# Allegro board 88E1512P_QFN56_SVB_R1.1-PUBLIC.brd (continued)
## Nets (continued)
N171469831: D2.2 R29.1
N192245170: D10.2 Q2.3(COLLECTOR)
N192245172: Q2.1(BASE) R127.2
N192284111: D8.2 Q1.3(COLLECTOR)
N192284251: Q1.1(BASE) R112.2

Pads without a net: SKT1 1 2 3 4; SKT2 1 2 3 4; U4 8 11; U6 13 14 15 16; U7 7; U8 7; U9 2 10; U10 2 10; U11 2 10; U12 2 10

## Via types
v1: diameter 0.559, hole 0.305, TOP to BOTTOM, 643 vias

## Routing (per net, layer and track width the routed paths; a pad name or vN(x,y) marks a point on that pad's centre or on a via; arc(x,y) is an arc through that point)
GND: length 1569
  TOP w0.254: v1(20.33,20.46) 19.81,20.98 U9.16 ; U10.16 156.6,175.69 v1(156.08,176.21) ; v1(176.4,178.75) 176.92,178.23 U12.16 ; U11.16 114.38,178.32 v1(113.86,177.8)
  TOP w0.508: C104.2 v1(146.43,40.13) ; v1(47.37,183.01) SW1.2 46.67,184.98 v1(46.1,184.4) ; J16.2 11.18,157.99 v1(11.18,157.1) ; v1(20.29,155.32) 20.29,154.41 J15.4 ; v1(87.38,155.32) 87.38,154.43 J12.5 ; J12.3 83.79,158.01 v1(83.79,157.1) ; J15.3 23.9,154.41 v1(23.9,155.32) ; v1(61.98,162.94) 61.98,162.05 J13.5 ; J11.5 100.08,154.43 v1(100.08,155.32) ; C128.2 57.44,20.84 v1(56.55,20.84) ; U7.10 v1(84.97,174.09) ; C115.2 v1(133.6,40.1) ; v1(71.09,164.72) 71.09,165.63 J14.3 ; J14.2 71.12,162.05 v1(71.12,162.94) ; J13.4 62,165.63 v1(62,164.72) ; J13.3 58.39,165.63 v1(58.39,164.72) ; U8.3 v1(32.15,174.09) ; C106.2 143.51,40.01 v1(143.38,40.13) ; J12.4 87.4,158.01 v1(87.4,157.1) ; v1(7.59,155.32) 7.59,154.41 J16.4 ; J14.4 74.7,165.63 v1(74.7,164.72) ; U7.9 v1(85.77,174.09) ; J18.2 20.19,119.25 v1(20.19,120.14) ; C135.2 v1(43.69,26.51) ; U7.1 v1(92.17,174.09) ; Q2.2 v1(119.57,168.97) ; J15.2 23.88,157.99 v1(23.88,157.1) ; U8.20 v1(34.15,168.81) ; v1(7.47,121.92) 7.47,122.83 J17.3 ; v1(23.77,121.92) 23.77,122.83 J18.4 ; J17.4 11.07,122.83 v1(11.07,121.92) ; C112.2 138.68,40.01 v1(138.81,40.13) ; v1(148.24,180.59) 148.85,180.59 C51.2 ; C125.2 v1(61.94,25.56) ; v1(96.49,157.1) 96.49,158.01 J11.3 ; J13.2 58.42,162.05 v1(58.42,162.94) ; J14.5 74.68,162.05 v1(74.68,162.94) ; C133.2 v1(43.69,24.29) ; v1(23.75,120.14) 23.75,119.25 J18.5 ; J16.3 11.2,154.41 v1(11.2,155.32) ; J11.4 100.1,158.01 v1(100.1,157.1) ; D9.2 164.77,163.83 v1(164.79,163.81) ; v1(59.56,20.84) 59.55,20.82 C129.2 ; C131.2 v1(46.23,20.82) ; J16.5 7.62,157.99 v1(7.62,157.1) ; v1(47.37,176.4) SW1.3 v1(47.37,180.09) ; C124.2 v1(61.94,26.67) ; v1(11.05,120.14) 11.05,119.25 J17.5 ; C130.2 v1(44.8,23.02) ; C134.2 v1(43.69,25.4) ; Y1.2 v1(167.51,100.33) ; v1(20.17,121.92) 20.17,122.83 J18.3 ; v1(59.63,182.02) 59.63,182.63 60.23,183.23 U3.1 ; v1(7.49,120.14) 7.49,119.25 J17.2 ; C132.2 v1(49.24,20.82) ; D11.2 v1(167.7,182.88) ; U7.17 v1(90.17,168.81) ; U8.11 v1(26.95,168.81) ; D7.2 v1(149.91,198.88) ; J15.5 20.32,157.99 v1(20.32,157.1) ; v1(96.52,155.32) 96.52,154.43 J11.2 ; C7.2 v1(168.56,89.54) C6.2 ; C107.2 141.48,40.01 v1(141.61,40.13) ; U8.14 v1(29.35,168.81) ; Y3.2 v1(74.68,99.89) ; v1(137.8,40.13) 137.67,40.01 C111.2 ; U8.9 v1(27.35,174.09) ; C108.2 v1(142.49,40.13) ; C102.2 145.42,40.01 v1(145.54,40.13) ; U8.17 v1(31.75,168.81) ; U8.10 v1(26.55,174.09) ; U8.1 v1(33.75,174.09) ; U7.11 v1(85.37,168.81) ; v1(83.82,155.32) 83.82,154.43 J12.2 ; U7.3 v1(90.57,174.09) ; C126.2 v1(61.94,24.45) ; C103.2 v1(147.57,40.13) ; Q1.2 v1(26.61,35.75) ; C116.2 v1(134.75,40.1) ; U7.20 v1(92.57,168.81) ; C114.2 v1(135.89,40.1) ; C127.2 v1(60.67,23.02) ; U7.14 v1(87.77,168.81) ; C110.2 v1(139.83,40.1)
  TOP w0.762: C123.1 v1(9.78,21.11) ; C122.1 v1(175.13,30.61)
  TOP w2.54: J21.1 J21.2
  L2_GND w1.27: TP11.1 23.41,107.53 ; TP11.1 21.8,109.14 ; TP11.1 21.8,107.53 ; TP11.1 23.41,109.14 ; TP4.1 24.55,77.77 ; TP4.1 22.94,76.16 ; TP4.1 22.94,77.77 ; TP4.1 24.55,76.16 ; J27.4 115.97,142.09 ; J27.4 115.97,144.42 ; J27.4 113.64,142.09 ; J27.4 113.64,144.42 ; J30.2 112.04,42.65 ; J30.2 112.04,44.98 ; J30.2 109.71,42.65 ; J30.2 109.71,44.98 ; 10.77,65.51 J29.5 ; J29.5 13.1,67.84 ; J29.5 10.77,67.84 ; J29.5 13.1,65.51 ; 7.49,98.68 8.66,97.51 ; 7.49,98.68 6.33,99.84 ; 7.49,98.68 8.66,99.84 ; 7.49,98.68 6.33,97.51 ; 188.45,125.75 189.61,124.59 ; 189.61,124.59 190.78,123.42 ; 189.61,124.59 188.45,123.42 ; 189.61,124.59 190.78,125.75 ; 94.09,76.98 J23.3 ; J23.3 96.41,76.98 ; J23.3 96.41,74.65 ; J23.3 94.09,74.65 ; J26.3 61.49,136.29 ; J26.3 59.16,133.96 ; J26.3 59.16,136.29 ; J26.3 61.49,133.96 ; 34.52,53.45 J31.4 ; J31.4 36.85,53.45 ; J31.4 34.52,55.77 ; J31.4 36.85,55.77 ; 5.69,60.43 J29.3 ; J29.3 5.69,62.76 ; J29.3 8.02,60.43 ; J29.3 8.02,62.76 ; 105.49,170.52 TP12.1 ; TP12.1 105.49,172.13 ; TP12.1 107.1,172.13 ; TP12.1 107.1,170.52 ; J9.4 139.06,192.28 ; J9.4 137.54,192.28 ; J9.4 139.06,193.8 ; J9.4 137.54,193.8 ; 7.2,81.96 TP13.1 ; TP13.1 8.81,81.96 ; TP13.1 7.2,80.35 ; TP13.1 8.81,80.35 ; 99.17,69.57 J23.5 ; J23.5 101.49,71.9 ; J23.5 101.49,69.57 ; J23.5 99.17,71.9 ; 84.18,82.4 J8.3 ; J8.3 86.51,82.4 ; J8.3 84.18,84.73 ; J8.3 86.51,84.73 ; JP1.2 182.67,98.64 ; JP1.2 181.06,100.25 ; JP1.2 181.06,98.64 ; JP1.2 182.67,100.25 ; J27.5 115.97,147.17 ; J27.5 113.64,149.5 ; J27.5 113.64,147.17 ; J27.5 115.97,149.5 ; 189.84,86.47 J6.5 ; J6.5 192.17,86.47 ; J6.5 192.17,88.79 ; J6.5 189.84,88.79 ; J3.2 163.6,141.75 ; J3.2 161.27,141.75 ; J3.2 161.27,139.42 ; J3.2 163.6,139.42 ; J31.5 36.85,60.85 ; J31.5 36.85,58.53 ; J31.5 34.52,58.53 ; J31.5 34.52,60.85 ; J22.2 176.81,151.62 ; J22.2 174.48,151.62 ; J22.2 174.48,153.95 ; J22.2 176.81,153.95 ; 94.47,105.56 J2.2 ; J2.2 94.47,103.23 ; J2.2 96.8,103.23 ; J2.2 96.8,105.56 ; 189.84,48.15 J19.5 ; J19.5 192.17,48.15 ; J19.5 192.17,45.83 ; J19.5 189.84,45.83 ; 15.58,170.01 TP3.1 ; TP3.1 15.58,171.62 ; TP3.1 17.19,171.62 ; TP3.1 17.19,170.01 ; J6.4 192.17,83.71 ; J6.4 189.84,81.39 ; J6.4 189.84,83.71 ; J6.4 192.17,81.39 ; J27.3 110.89,142.09 ; J27.3 108.56,144.42 ; J27.3 108.56,142.09 ; J27.3 110.89,144.42 ; J6.2 187.09,88.79 ; J6.2 184.76,86.47 ; J6.2 187.09,86.47 ; J6.2 184.76,88.79 ; 65.41,135.13 66.57,133.96 ; 65.41,135.13 64.24,136.29 ; 65.41,135.13 66.57,136.29 ; 65.41,135.13 64.24,133.96 ; 84.18,87.48 J8.2 ; J8.2 86.51,87.48 ; J8.2 86.51,89.81 ; J8.2 84.18,89.81 ; 145.52,145.44 J24.3 ; J24.3 145.52,143.11 ; J24.3 147.85,143.11 ; J24.3 147.85,145.44 ; 92.18,50.69 J28.3 ; J28.3 94.51,50.69 ; J28.3 94.51,48.37 ; J28.3 92.18,48.37 ; J19.3 187.09,40.75 ; J19.3 184.76,43.07 ; J19.3 187.09,43.07 ; J19.3 184.76,40.75 ; J30.3 112.04,39.9 ; J30.3 109.71,39.9 ; J30.3 109.71,37.57 ; J30.3 112.04,37.57 ; 10.77,60.43 J29.4 ; J29.4 13.1,62.76 ; J29.4 13.1,60.43 ; J29.4 10.77,62.76 ; 5.69,67.84 J29.2 ; J29.2 8.02,65.51 ; J29.2 8.02,67.84 ; J29.2 5.69,65.51 ; 193.02,99.59 194.18,98.43 ; 194.18,98.43 195.35,99.59 ; 194.18,98.43 195.35,97.26 ; 194.18,98.43 193.02,97.26 ; 87.1,50.69 88.27,49.53 ; 88.27,49.53 89.43,50.69 ; 88.27,49.53 87.1,48.37 ; 88.27,49.53 89.43,48.37 ; 82.76,104.44 JP7.2 ; JP7.2 84.37,104.44 ; JP7.2 84.37,102.83 ; JP7.2 82.76,102.83 ; J22.3 176.81,148.87 ; J22.3 174.48,148.87 ; J22.3 176.81,146.54 ; J22.3 174.48,146.54 ; 99.55,105.56 J2.5 ; J2.5 101.88,103.23 ; J2.5 99.55,103.23 ; J2.5 101.88,105.56 ; 175.6,50.63 JP6.2 ; JP6.2 177.21,52.24 ; JP6.2 175.6,52.24 ; JP6.2 177.21,50.63 ; 184.49,187.5 TP9.1 ; TP9.1 186.1,185.88 ; TP9.1 184.49,185.88 ; TP9.1 186.1,187.5 ; J31.3 31.77,55.77 ; J31.3 31.77,53.45 ; J31.3 29.44,53.45 ; J31.3 29.44,55.77 ; 33.1,20.53 TP10.1 ; TP10.1 34.71,22.14 ; TP10.1 34.71,20.53 ; TP10.1 33.1,22.14 ; 114.79,39.9 115.95,38.73 ; 115.95,38.73 114.79,37.57 ; 115.95,38.73 117.12,37.57 ; 115.95,38.73 117.12,39.9 ; J4.3 190.78,120.67 ; J4.3 190.78,118.34 ; J4.3 188.45,120.67 ; J4.3 188.45,118.34 ; 173.06,45.26 TP5.1 ; TP5.1 173.06,43.64 ; TP5.1 174.67,43.64 ; TP5.1 174.67,45.26 ; 11.41,97.51 12.57,98.68 ; 12.57,98.68 13.74,99.84 ; 12.57,98.68 11.41,99.84 ; 12.57,98.68 13.74,97.51 ; 6.33,94.76 J10.3 ; J10.3 8.66,92.43 ; J10.3 6.33,92.43 ; J10.3 8.66,94.76 ; 89.26,89.81 J8.5 ; J8.5 91.59,87.48 ; J8.5 89.26,87.48 ; J8.5 91.59,89.81 ; 193.53,125.75 194.69,124.59 ; 194.69,124.59 193.53,123.42 ; 194.69,124.59 195.86,123.42 ; 194.69,124.59 195.86,125.75 ; J31.2 31.77,60.85 ; J31.2 29.44,58.53 ; J31.2 31.77,58.53 ; J31.2 29.44,60.85 ; 64.24,139.04 65.41,140.21 ; 65.41,140.21 64.24,141.37 ; 65.41,140.21 66.57,139.04 ; 65.41,140.21 66.57,141.37 ; 179.56,148.87 J22.4 ; J22.4 179.56,146.54 ; J22.4 181.89,148.87 ; J22.4 181.89,146.54 ; 173.08,192.93 J21.1 ; J21.1 175.41,192.93 ; J21.1 173.08,190.61 ; J21.1 175.41,190.61 ; 193.02,102.34 J1.5 ; J1.5 195.35,102.34 ; J1.5 193.02,104.67 ; J1.5 195.35,104.67 ; 22.69,88.09 JP8.2 ; JP8.2 22.69,89.71 ; JP8.2 24.3,89.71 ; JP8.2 24.3,88.09 ; 184.76,62.97 J7.2 ; J7.2 187.09,62.97 ; J7.2 184.76,65.3 ; J7.2 187.09,65.3 ; 145.52,148.19 J24.2 ; J24.2 145.52,150.52 ; J24.2 147.85,150.52 ; J24.2 147.85,148.19 ; J28.4 94.51,53.45 ; J28.4 94.51,55.77 ; J28.4 92.18,53.45 ; J28.4 92.18,55.77 ; 88.27,54.61 89.43,53.45 ; 88.27,54.61 87.1,53.45 ; 88.27,54.61 87.1,55.77 ; 88.27,54.61 89.43,55.77 ; J2.4 101.88,98.15 ; J2.4 99.55,100.48 ; J2.4 101.88,100.48 ; J2.4 99.55,98.15 ; 63.84,179.88 JP2.1 ; JP2.1 63.84,178.26 ; JP2.1 65.45,179.88 ; JP2.1 65.45,178.26 ; J5.2 190.78,140.44 ; J5.2 190.78,142.77 ; J5.2 188.45,140.44 ; J5.2 188.45,142.77 ; 187.94,104.67 J1.2 ; J1.2 190.27,104.67 ; J1.2 190.27,102.34 ; J1.2 187.94,102.34 ; 189.84,60.22 J7.4 ; J7.4 189.84,57.89 ; J7.4 192.17,60.22 ; J7.4 192.17,57.89 ; J27.2 110.89,149.5 ; J27.2 108.56,147.17 ; J27.2 108.56,149.5 ; J27.2 110.89,147.17 ; 114.79,44.98 115.95,43.81 ; 115.95,43.81 114.79,42.65 ; 115.95,43.81 117.12,44.98 ; 115.95,43.81 117.12,42.65 ; J19.2 187.09,48.15 ; J19.2 184.76,45.83 ; J19.2 184.76,48.15 ; J19.2 187.09,45.83 ; 39.09,133.96 J25.3 ; J25.3 39.09,136.29 ; J25.3 41.42,133.96 ; J25.3 41.42,136.29 ; 166.35,139.42 J3.5 ; J3.5 168.68,139.42 ; J3.5 166.35,141.75 ; J3.5 168.68,141.75 ; J7.3 187.09,60.22 ; J7.3 187.09,57.89 ; J7.3 184.76,57.89 ; J7.3 184.76,60.22 ; J25.2 41.42,139.04 ; J25.2 41.42,141.37 ; J25.2 39.09,141.37 ; J25.2 39.09,139.04 ; J4.4 195.86,120.67 ; J4.4 195.86,118.34 ; J4.4 193.53,120.67 ; J4.4 193.53,118.34 ; 99.17,76.98 J23.2 ; J23.2 101.49,76.98 ; J23.2 99.17,74.65 ; J23.2 101.49,74.65 ; 89.26,82.4 J8.4 ; J8.4 91.59,82.4 ; J8.4 89.26,84.73 ; J8.4 91.59,84.73 ; 44.17,133.96 J25.4 ; J25.4 46.5,133.96 ; J25.4 44.17,136.29 ; J25.4 46.5,136.29 ; 173.08,200.77 J21.2 ; J21.2 175.41,203.09 ; J21.2 175.41,200.77 ; J21.2 173.08,203.09 ; 12.57,93.6 13.74,94.76 ; 12.57,93.6 11.41,92.43 ; 12.57,93.6 13.74,92.43 ; 12.57,93.6 11.41,94.76 ; 150.6,143.11 J24.4 ; J24.4 152.93,145.44 ; J24.4 150.6,145.44 ; J24.4 152.93,143.11 ; JP4.2 99.36,87.29 ; JP4.2 97.75,85.68 ; JP4.2 99.36,85.68 ; JP4.2 97.75,87.29 ; J3.3 163.6,136.67 ; J3.3 161.27,134.34 ; J3.3 163.6,134.34 ; J3.3 161.27,136.67 ; 189.84,62.97 J7.5 ; J7.5 192.17,62.97 ; J7.5 189.84,65.3 ; J7.5 192.17,65.3 ; J2.3 96.8,100.48 ; J2.3 94.47,98.15 ; J2.3 96.8,98.15 ; J2.3 94.47,100.48 ; 136.23,179.53 TP2.1 ; TP2.1 137.84,179.53 ; TP2.1 137.84,181.15 ; TP2.1 136.23,181.15 ; TP8.1 106.22,24.47 ; TP8.1 106.22,26.08 ; TP8.1 104.6,24.47 ; TP8.1 104.6,26.08 ; J5.4 195.86,135.36 ; J5.4 195.86,137.69 ; J5.4 193.53,135.36 ; J5.4 193.53,137.69 ; 166.35,136.67 J3.4 ; J3.4 166.35,134.34 ; J3.4 168.68,134.34 ; J3.4 168.68,136.67 ; J5.3 190.78,135.36 ; J5.3 188.45,135.36 ; J5.3 190.78,137.69 ; J5.3 188.45,137.69 ; 138.81,189.74 J9.3 ; J9.3 138.81,191.26 ; J9.3 140.33,191.26 ; J9.3 140.33,189.74 ; J5.5 195.86,142.77 ; J5.5 193.53,142.77 ; J5.5 193.53,140.44 ; J5.5 195.86,140.44 ; J24.5 152.93,148.19 ; J24.5 150.6,148.19 ; J24.5 152.93,150.52 ; J24.5 150.6,150.52 ; 187.94,99.59 189.1,98.43 ; 189.1,98.43 190.27,97.26 ; 189.1,98.43 187.94,97.26 ; 189.1,98.43 190.27,99.59 ; 58.12,176.07 TP1.1 ; TP1.1 59.73,174.45 ; TP1.1 58.12,174.45 ; TP1.1 59.73,176.07 ; J6.3 187.09,83.71 ; J6.3 184.76,83.71 ; J6.3 187.09,81.39 ; J6.3 184.76,81.39 ; J26.2 61.49,139.04 ; J26.2 61.49,141.37 ; J26.2 59.16,139.04 ; J26.2 59.16,141.37 ; J19.4 192.17,40.75 ; J19.4 192.17,43.07 ; J19.4 189.84,40.75 ; J19.4 189.84,43.07 ; 94.09,69.57 J23.4 ; J23.4 94.09,71.9 ; J23.4 96.41,69.57 ; J23.4 96.41,71.9 ; J25.5 46.5,139.04 ; J25.5 44.17,139.04 ; J25.5 44.17,141.37 ; J25.5 46.5,141.37 ; 79.71,69.3 JP10.2 ; JP10.2 81.32,70.91 ; JP10.2 81.32,69.3 ; JP10.2 79.71,70.91 ; J22.5 181.89,151.62 ; J22.5 179.56,153.95 ; J22.5 181.89,153.95 ; J22.5 179.56,151.62
  L5_GND w1.27: 39.09,133.96 J25.3 ; J25.3 41.42,133.96 ; J25.3 39.09,136.29 ; J25.3 41.42,136.29 ; J8.4 91.59,84.73 ; J8.4 89.26,84.73 ; J8.4 91.59,82.4 ; J8.4 89.26,82.4 ; 44.17,133.96 J25.4 ; J25.4 46.5,136.29 ; J25.4 46.5,133.96 ; J25.4 44.17,136.29 ; J5.2 190.78,140.44 ; J5.2 190.78,142.77 ; J5.2 188.45,142.77 ; J5.2 188.45,140.44 ; 114.79,42.65 115.95,43.81 ; 115.95,43.81 117.12,44.98 ; 115.95,43.81 114.79,44.98 ; 115.95,43.81 117.12,42.65 ; 6.33,97.51 7.49,98.68 ; 7.49,98.68 8.66,99.84 ; 7.49,98.68 6.33,99.84 ; 7.49,98.68 8.66,97.51 ; 187.94,97.26 189.1,98.43 ; 189.1,98.43 187.94,99.59 ; 189.1,98.43 190.27,99.59 ; 189.1,98.43 190.27,97.26 ; 11.41,94.76 12.57,93.6 ; 12.57,93.6 13.74,92.43 ; 12.57,93.6 11.41,92.43 ; 12.57,93.6 13.74,94.76 ; 92.18,48.37 J28.3 ; J28.3 92.18,50.69 ; J28.3 94.51,48.37 ; J28.3 94.51,50.69 ; 184.76,65.3 J7.2 ; J7.2 184.76,62.97 ; J7.2 187.09,62.97 ; J7.2 187.09,65.3 ; J23.4 96.41,69.57 ; J23.4 96.41,71.9 ; J23.4 94.09,71.9 ; J23.4 94.09,69.57 ; J27.4 115.97,142.09 ; J27.4 113.64,142.09 ; J27.4 115.97,144.42 ; J27.4 113.64,144.42 ; 184.49,187.5 TP9.1 ; TP9.1 184.49,185.88 ; TP9.1 186.1,187.5 ; TP9.1 186.1,185.88 ; J29.3 8.02,62.76 ; J29.3 5.69,62.76 ; J29.3 8.02,60.43 ; J29.3 5.69,60.43 ; 34.52,53.45 J31.4 ; J31.4 36.85,55.77 ; J31.4 34.52,55.77 ; J31.4 36.85,53.45 ; JP8.2 24.3,88.09 ; JP8.2 24.3,89.71 ; JP8.2 22.69,89.71 ; JP8.2 22.69,88.09 ; 114.79,39.9 115.95,38.73 ; 115.95,38.73 114.79,37.57 ; 115.95,38.73 117.12,39.9 ; 115.95,38.73 117.12,37.57 ; 138.81,189.74 J9.3 ; J9.3 140.33,191.26 ; J9.3 140.33,189.74 ; J9.3 138.81,191.26 ; J19.3 187.09,40.75 ; J19.3 184.76,40.75 ; J19.3 184.76,43.07 ; J19.3 187.09,43.07 ; J2.5 101.88,105.56 ; J2.5 99.55,105.56 ; J2.5 99.55,103.23 ; J2.5 101.88,103.23 ; 193.02,104.67 J1.5 ; J1.5 193.02,102.34 ; J1.5 195.35,104.67 ; J1.5 195.35,102.34 ; J25.5 46.5,139.04 ; J25.5 44.17,141.37 ; J25.5 46.5,141.37 ; J25.5 44.17,139.04 ; J30.3 112.04,39.9 ; J30.3 112.04,37.57 ; J30.3 109.71,39.9 ; J30.3 109.71,37.57 ; J25.2 41.42,141.37 ; J25.2 39.09,139.04 ; J25.2 39.09,141.37 ; J25.2 41.42,139.04 ; 193.02,97.26 194.18,98.43 ; 194.18,98.43 195.35,97.26 ; 194.18,98.43 193.02,99.59 ; 194.18,98.43 195.35,99.59 ; J8.3 86.51,84.73 ; J8.3 86.51,82.4 ; J8.3 84.18,84.73 ; J8.3 84.18,82.4 ; 161.27,141.75 J3.2 ; J3.2 163.6,141.75 ; J3.2 163.6,139.42 ; J3.2 161.27,139.42 ; 82.76,104.44 JP7.2 ; JP7.2 82.76,102.83 ; JP7.2 84.37,104.44 ; JP7.2 84.37,102.83 ; J6.3 187.09,81.39 ; J6.3 187.09,83.71 ; J6.3 184.76,81.39 ; J6.3 184.76,83.71 ; 189.84,65.3 J7.5 ; J7.5 189.84,62.97 ; J7.5 192.17,65.3 ; J7.5 192.17,62.97 ; JP4.2 99.36,87.29 ; JP4.2 97.75,85.68 ; JP4.2 99.36,85.68 ; JP4.2 97.75,87.29 ; JP1.2 182.67,98.64 ; JP1.2 181.06,100.25 ; JP1.2 182.67,100.25 ; JP1.2 181.06,98.64 ; 59.16,133.96 J26.3 ; J26.3 61.49,133.96 ; J26.3 61.49,136.29 ; J26.3 59.16,136.29 ; J3.3 163.6,136.67 ; J3.3 161.27,134.34 ; J3.3 163.6,134.34 ; J3.3 161.27,136.67 ; J2.3 96.8,100.48 ; J2.3 96.8,98.15 ; J2.3 94.47,98.15 ; J2.3 94.47,100.48 ; 87.1,48.37 88.27,49.53 ; 88.27,49.53 89.43,50.69 ; 88.27,49.53 89.43,48.37 ; 88.27,49.53 87.1,50.69 ; 188.45,135.36 J5.3 ; J5.3 190.78,137.69 ; J5.3 190.78,135.36 ; J5.3 188.45,137.69 ; 15.58,171.62 TP3.1 ; TP3.1 17.19,171.62 ; TP3.1 17.19,170.01 ; TP3.1 15.58,170.01 ; J31.3 31.77,53.45 ; J31.3 29.44,55.77 ; J31.3 31.77,55.77 ; J31.3 29.44,53.45 ; 174.48,151.62 J22.2 ; J22.2 176.81,151.62 ; J22.2 174.48,153.95 ; J22.2 176.81,153.95 ; J27.5 115.97,147.17 ; J27.5 115.97,149.5 ; J27.5 113.64,149.5 ; J27.5 113.64,147.17 ; 193.53,137.69 J5.4 ; J5.4 195.86,137.69 ; J5.4 193.53,135.36 ; J5.4 195.86,135.36 ; 184.76,45.83 J19.2 ; J19.2 184.76,48.15 ; J19.2 187.09,45.83 ; J19.2 187.09,48.15 ; J27.3 110.89,144.42 ; J27.3 108.56,142.09 ; J27.3 110.89,142.09 ; J27.3 108.56,144.42 ; 7.2,81.96 TP13.1 ; TP13.1 7.2,80.35 ; TP13.1 8.81,81.96 ; TP13.1 8.81,80.35 ; J7.4 192.17,57.89 ; J7.4 192.17,60.22 ; J7.4 189.84,57.89 ; J7.4 189.84,60.22 ; J3.4 168.68,136.67 ; J3.4 166.35,136.67 ; J3.4 168.68,134.34 ; J3.4 166.35,134.34 ; J26.2 61.49,141.37 ; J26.2 59.16,139.04 ; J26.2 59.16,141.37 ; J26.2 61.49,139.04 ; 22.94,77.77 TP4.1 ; TP4.1 24.55,76.16 ; TP4.1 22.94,76.16 ; TP4.1 24.55,77.77 ; 193.53,118.34 J4.4 ; J4.4 195.86,118.34 ; J4.4 193.53,120.67 ; J4.4 195.86,120.67 ; 175.6,52.24 JP6.2 ; JP6.2 177.21,52.24 ; JP6.2 175.6,50.63 ; JP6.2 177.21,50.63 ; J21.2 175.41,203.09 ; J21.2 173.08,203.09 ; J21.2 173.08,200.77 ; J21.2 175.41,200.77 ; J22.3 176.81,148.87 ; J22.3 174.48,148.87 ; J22.3 176.81,146.54 ; J22.3 174.48,146.54 ; J6.5 192.17,88.79 ; J6.5 189.84,88.79 ; J6.5 192.17,86.47 ; J6.5 189.84,86.47 ; J5.5 195.86,142.77 ; J5.5 193.53,140.44 ; J5.5 193.53,142.77 ; J5.5 195.86,140.44 ; 166.35,141.75 J3.5 ; J3.5 168.68,139.42 ; J3.5 168.68,141.75 ; J3.5 166.35,139.42 ; 99.17,74.65 J23.2 ; J23.2 99.17,76.98 ; J23.2 101.49,74.65 ; J23.2 101.49,76.98 ; 21.8,109.14 TP11.1 ; TP11.1 23.41,107.53 ; TP11.1 23.41,109.14 ; TP11.1 21.8,107.53 ; 92.18,55.77 J28.4 ; J28.4 94.51,53.45 ; J28.4 92.18,53.45 ; J28.4 94.51,55.77 ; TP1.1 59.73,176.07 ; TP1.1 58.12,176.07 ; TP1.1 58.12,174.45 ; TP1.1 59.73,174.45 ; 65.41,140.21 66.57,141.37 ; 65.41,140.21 64.24,139.04 ; 65.41,140.21 64.24,141.37 ; 65.41,140.21 66.57,139.04 ; J4.3 190.78,120.67 ; J4.3 188.45,120.67 ; J4.3 188.45,118.34 ; J4.3 190.78,118.34 ; 29.44,58.53 J31.2 ; J31.2 31.77,58.53 ; J31.2 31.77,60.85 ; J31.2 29.44,60.85 ; 5.69,65.51 J29.2 ; J29.2 5.69,67.84 ; J29.2 8.02,67.84 ; J29.2 8.02,65.51 ; 136.23,181.15 TP2.1 ; TP2.1 137.84,181.15 ; TP2.1 137.84,179.53 ; TP2.1 136.23,179.53 ; J23.3 96.41,74.65 ; J23.3 96.41,76.98 ; J23.3 94.09,74.65 ; J23.3 94.09,76.98 ; J19.4 192.17,40.75 ; J19.4 189.84,43.07 ; J19.4 192.17,43.07 ; J19.4 189.84,40.75 ; 99.55,100.48 J2.4 ; J2.4 101.88,100.48 ; J2.4 101.88,98.15 ; J2.4 99.55,98.15 ; J6.2 187.09,88.79 ; J6.2 187.09,86.47 ; J6.2 184.76,88.79 ; J6.2 184.76,86.47 ; 189.84,45.83 J19.5 ; J19.5 192.17,45.83 ; J19.5 189.84,48.15 ; J19.5 192.17,48.15 ; J2.2 96.8,103.23 ; J2.2 94.47,105.56 ; J2.2 94.47,103.23 ; J2.2 96.8,105.56 ; 11.41,97.51 12.57,98.68 ; 12.57,98.68 13.74,97.51 ; 12.57,98.68 11.41,99.84 ; 12.57,98.68 13.74,99.84 ; J7.3 187.09,57.89 ; J7.3 187.09,60.22 ; J7.3 184.76,57.89 ; J7.3 184.76,60.22 ; J29.4 13.1,60.43 ; J29.4 10.77,62.76 ; J29.4 10.77,60.43 ; J29.4 13.1,62.76 ; 10.77,65.51 J29.5 ; J29.5 10.77,67.84 ; J29.5 13.1,67.84 ; J29.5 13.1,65.51 ; 88.27,54.61 89.43,53.45 ; 88.27,54.61 87.1,55.77 ; 88.27,54.61 89.43,55.77 ; 88.27,54.61 87.1,53.45 ; 150.6,145.44 J24.4 ; J24.4 150.6,143.11 ; J24.4 152.93,143.11 ; J24.4 152.93,145.44 ; 99.17,69.57 J23.5 ; J23.5 101.49,71.9 ; J23.5 101.49,69.57 ; J23.5 99.17,71.9 ; 64.24,133.96 65.41,135.13 ; 65.41,135.13 64.24,136.29 ; 65.41,135.13 66.57,133.96 ; 65.41,135.13 66.57,136.29 ; 33.1,20.53 TP10.1 ; TP10.1 33.1,22.14 ; TP10.1 34.71,20.53 ; TP10.1 34.71,22.14 ; 173.06,43.64 TP5.1 ; TP5.1 174.67,45.26 ; TP5.1 174.67,43.64 ; TP5.1 173.06,45.26 ; J24.2 147.85,148.19 ; J24.2 147.85,150.52 ; J24.2 145.52,150.52 ; J24.2 145.52,148.19 ; J6.4 192.17,81.39 ; J6.4 189.84,81.39 ; J6.4 189.84,83.71 ; J6.4 192.17,83.71 ; 105.49,172.13 TP12.1 ; TP12.1 107.1,172.13 ; TP12.1 107.1,170.52 ; TP12.1 105.49,170.52 ; 34.52,58.53 J31.5 ; J31.5 34.52,60.85 ; J31.5 36.85,60.85 ; J31.5 36.85,58.53 ; J8.2 86.51,87.48 ; J8.2 86.51,89.81 ; J8.2 84.18,87.48 ; J8.2 84.18,89.81 ; 150.6,148.19 J24.5 ; J24.5 152.93,148.19 ; J24.5 152.93,150.52 ; J24.5 150.6,150.52 ; 104.6,24.47 TP8.1 ; TP8.1 106.22,24.47 ; TP8.1 104.6,26.08 ; TP8.1 106.22,26.08 ; J21.1 175.41,190.61 ; J21.1 173.08,190.61 ; J21.1 173.08,192.93 ; J21.1 175.41,192.93 ; 193.53,125.75 194.69,124.59 ; 194.69,124.59 195.86,123.42 ; 194.69,124.59 195.86,125.75 ; 194.69,124.59 193.53,123.42 ; J22.4 181.89,148.87 ; J22.4 181.89,146.54 ; J22.4 179.56,148.87 ; J22.4 179.56,146.54 ; 108.56,147.17 J27.2 ; J27.2 108.56,149.5 ; J27.2 110.89,147.17 ; J27.2 110.89,149.5 ; J1.2 190.27,104.67 ; J1.2 187.94,102.34 ; J1.2 190.27,102.34 ; J1.2 187.94,104.67 ; 63.84,179.88 JP2.1 ; JP2.1 65.45,178.26 ; JP2.1 63.84,178.26 ; JP2.1 65.45,179.88 ; J22.5 181.89,153.95 ; J22.5 179.56,151.62 ; J22.5 179.56,153.95 ; J22.5 181.89,151.62 ; 189.61,124.59 190.78,123.42 ; 189.61,124.59 188.45,123.42 ; 189.61,124.59 190.78,125.75 ; 189.61,124.59 188.45,125.75 ; J10.3 8.66,94.76 ; J10.3 6.33,94.76 ; J10.3 6.33,92.43 ; J10.3 8.66,92.43 ; J8.5 91.59,89.81 ; J8.5 91.59,87.48 ; J8.5 89.26,89.81 ; J8.5 89.26,87.48 ; JP10.2 81.32,70.91 ; JP10.2 79.71,70.91 ; JP10.2 81.32,69.3 ; JP10.2 79.71,69.3 ; J9.4 139.06,193.8 ; J9.4 137.54,193.8 ; J9.4 139.06,192.28 ; J9.4 137.54,192.28 ; 145.52,145.44 J24.3 ; J24.3 145.52,143.11 ; J24.3 147.85,145.44 ; J24.3 147.85,143.11 ; 109.71,42.65 J30.2 ; J30.2 112.04,42.65 ; J30.2 112.04,44.98 ; J30.2 109.71,44.98
  BOTTOM w0.152: R13.2 v1(149.58,87.15)
  BOTTOM w0.508: C177.2 v1(95.5,118.62) ; C68.2 v1(42.93,112.55) ; R15.2 v1(174.49,71.59) ; C58.2 48.77,90.96 ; 48.77,90.96 C67.2 ; 48.77,90.96 49.43,90.96 v1(49.55,91.08) ; C159.2 v1(167.51,191.77) ; C72.2 48.77,94.62 48.45,94.93 v1(48.45,95.41) ; C78.2 v1(60.3,69.59) ; C55.2 v1(80.36,86.83) ; C69.2 v1(38.18,89.86) ; C182.2 v1(28.96,100.85) ; C13.2 v1(139.04,91.31) ; C198.2 75.28,108.78 v1(74.2,108.78) ; U4.12 v1(150.74,181.86) ; C35.2 144.24,91.92 v1(143.64,91.31) ; R154.2 v1(44.2,119.15) ; C96.2 v1(69.99,92.87) ; C1.2 171.67,96.84 v1(171.05,96.84) ; C141.2 90.49,174.18 v1(90.57,174.09) ; C44.2 v1(141.16,73.56) ; C80.2 v1(49.37,83) ; C36.2 v1(141.16,78.62) ; R153.2 v1(41.66,119.15) ; C46.2 v1(152.72,92.11) ; C140.2 v1(84.33,169.71) ; v1(93.53,169.85) 94.35,169.85 C143.2 ; C74.2 v1(47.99,101.23) ; 53.09,88.01 v1(53.09,88.41) ; 53.09,88.01 53.14,88.01 53.52,87.63 C88.2 ; 53.09,88.01 52.71,87.64 C89.2 ; v1(144.26,94.3) 144.26,94.69 143.86,95.09 C16.2 ; C161.2 v1(163.7,53.75) ; C90.2 v1(54.61,85.66) ; C9.2 145.13,94.59 v1(145,94.46) ; C97.2 v1(65.09,95.85) ; C20.2 128.68,87.63 v1(128.67,87.64) ; C56.2 v1(76.71,86.52) ; C208.2 v1(31.75,64.22) ; v1(53.97,94.48) 53.92,94.53 53.92,94.57 53.82,94.67 C65.2 ; C60.2 v1(45.34,112.5) ; C85.2 v1(74.43,82.66) ; C25.2 138.3,95.25 v1(137.99,95.57) ; C151.2 32.23,174.17 v1(32.15,174.09) ; C204.2 v1(100.77,65.43) ; C173.2 v1(77.98,63.78) ; C94.2 v1(61.92,95.85) ; C14.2 v1(95,101.85) ; R124.1 v1(153.86,170.65) ; C86.2 v1(63.36,69.59) ; R146.1 v1(88.27,45.45) ; C42.2 v1(141.16,81.8) ; R161.2 v1(132.59,138.92) ; C54.2 v1(91.06,86.11) ; 194.18,98.43 194,98.61 C3.2 194,103.32 J1.5 ; C87.2 49.59,88.45 49.66,88.52 v1(49.66,88.67) ; R151.2 v1(36.58,119.15) ; C162.2 v1(167.63,49.28) ; R25.2 v1(60.04,87.15) ; C49.2 v1(159.52,91.28) ; C31.2 v1(159.52,87.62) ; C93.2 v1(62.1,91.95) ; C95.2 v1(65.09,92.43) ; 7.49,98.68 7.52,98.65 C63.2 7.52,93.63 J10.3 ; C34.2 v1(144.65,89.19) ; C207.2 v1(35.49,65.34) ; C184.2 v1(31.97,106.68) ; C43.2 142.59,89.67 v1(142.59,90.01) ; U4.10 v1(150.78,184.4) ; C4.2 59.63,181.32 v1(59.63,182.02) 59.63,182.66 C5.2 ; R115.1 v1(21.62,26.87) ; C174.2 v1(28.8,45.88) ; C27.2 127.4,98.27 v1(127.35,98.27) ; C150.2 v1(35.11,169.71) ; R134.1 v1(174.02,173.03) ; C82.2 v1(62.26,93.5) ; C62.2 v1(75.07,104.19) ; C73.2 v1(38.98,96.53) ; v1(56.71,95.41) 56.39,95.09 C64.2 ; C33.2 139.89,89.38 v1(140.37,89.85) 140.87,89.35 C41.2 ; v1(54.48,91.44) 54.48,91.47 C81.2 ; C59.2 57.78,96.59 v1(58.55,96.59) ; C196.2 v1(182.6,108.42) ; R152.2 v1(39.12,119.15) ; U4.7 v1(142.88,186.94) ; R156.2 v1(49.28,119.15) ; C70.2 v1(42.42,89.69) ; R27.2 v1(82.12,74.55) ; C66.2 v1(50.38,94.43) ; C53.2 v1(81.63,97.47) ; C92.2 v1(51.56,85.66) ; C8.2 v1(146.59,96.97) ; R155.2 v1(46.74,119.15) ; C28.2 v1(133.41,95.85) ; C48.2 v1(152.72,93.98) ; R14.2 v1(174.49,75.09) ; v1(118.96,176.46) 118.96,175.76 R129.1 ; C79.2 56.18,89.99 v1(55.61,89.99) ; U4.9 v1(150.75,185.67) ; C29.2 v1(147.33,87.47) ; C83.2 v1(55.24,89.19) ; R159.2 v1(130.05,138.92) ; v1(139.91,94.44) 139.92,94.45 C18.2 ; C52.2 v1(84.93,100.99) ; C10.2 v1(149.57,96.04) ; C176.2 v1(101.6,118.67) ; C37.2 v1(165.34,81.29) ; C175.2 v1(34.18,45.09) ; R26.2 v1(82.12,77.09) ; v1(171.8,99.7) 172.72,99.7 C2.2 ; C172.2 v1(82.26,59.31) ; C138.2 v1(86.12,172.08) ; C21.2 v1(139.07,88.77) ; C191.2 v1(53.02,147.57) ; C91.2 v1(53.8,69.59) ; C142.2 v1(85.6,169.86) ; R147.1 v1(10.03,57.89) ; C163.2 v1(122.17,49.28) ; C185.2 v1(134.07,153) ; C170.2 v1(74.01,63.78) ; C38.2 v1(143.54,73.5) ; C45.2 v1(143.54,78.9) ; C47.2 v1(153.34,97.16) ; C57.2 v1(39.88,91.44) ; R157.2 v1(122.43,138.92) ; C84.2 v1(53.69,79) ; C77.2 v1(69.99,88.28) ; C149.2 v1(34.02,170.02) ; C76.2 v1(57.47,87.31) ; C19.2 v1(140.83,107.69) ; C17.2 v1(133.41,88.94) ; C30.2 v1(147.19,67.79) ; U4.13 v1(148.24,180.59) ; C32.2 v1(143.54,90.17) ; C186.2 v1(136.27,147.8) ; C26.2 v1(136.07,74.67) ; C148.2 v1(28.89,173.17) ; C139.2 v1(92.27,169.86) ; C197.2 v1(81.28,108.2) ; C195.2 v1(180.09,106.69) ; C50.2 v1(149.87,91.94) ; C193.2 v1(53.97,149.48) ; C157.2 v1(157.35,53.75) ; R160.2 v1(127.51,138.92) ; C153.2 v1(25.91,169.71) ; C11.2 v1(159.52,95.87) ; C152.2 v1(27.17,170.02) ; R162.2 v1(135.38,138.92) ; C158.2 v1(161.48,49.28) ; C206.2 v1(99.02,60.57) ; C75.2 v1(44.65,93.65) ; C39.2 v1(147.19,73.5) ; C171.2 v1(69.88,59.31) ; C12.2 v1(151.14,107.81) ; C61.2 v1(69.99,98.44) ; C40.2 v1(143.54,81.76) ; C164.2 v1(123.47,53.75) ; R158.2 v1(124.97,138.92)
  BOTTOM w0.762: R62.2 v1(9.78,21.11) ; R63.2 v1(175.13,30.61)
  BOTTOM w1.016: C160.2 172.59,198.75 174.24,200.41 J21.2
  vias: v1(10.03,145.41) v1(13.56,111.82) v1(13.72,146.94) v1(17.68,111.66) v1(17.78,146.94) v1(20.19,30.99) v1(20.19,27.81) v1(20.43,25.59) v1(20.83,29.72) v1(20.95,80.14) v1(21.46,30.99) v1(21.46,28.45) v1(26.54,84.45) v1(30.1,129.79) v1(31.5,163.45) v1(32.38,82.17) v1(34.54,163.45) v1(36.83,116.46) v1(39.56,44.77) v1(44.64,44.77) v1(46.39,102.87) v1(47.18,44.77) v1(48.77,103.82) v1(50.67,93.34) v1(50.67,91.31) v1(50.67,89.54) v1(51,101.92) v1(52.26,44.77) v1(52.58,93.34) v1(52.58,91.19) v1(52.58,89.54) v1(53.85,93.34) v1(54.01,106.68) v1(54.23,89.92) v1(54.8,44.77) v1(55.91,103.66) v1(59.88,44.77) v1(62.42,44.77) v1(67.5,44.77) v1(70.68,150.81) v1(71.15,155.89) v1(72.42,124.46) v1(73.53,119.54) v1(74.64,155.89) v1(74.8,120.17) v1(75.12,150.81) v1(76.07,120.81) v1(77.34,121.44) v1(78.61,121.76) v1(80.84,127.64) v1(83.06,132.56) v1(83.06,127.64) v1(84.33,132.08) v1(86.74,141.1) v1(86.74,136.91) v1(90.84,145.41) v1(93.98,162.69) v1(95.12,145.41) v1(107.7,68.45) v1(115.44,81.53) v1(117.09,75.95) v1(118.89,177.52) v1(119.63,131.44) v1(120.41,176.51) v1(121.2,177.31) v1(121.79,83.69) v1(121.93,176.51) v1(122.73,177.31) v1(123.83,88.39) v1(128.3,91.44) v1(130.81,44.45) v1(133.6,92.08) v1(134.87,44.45) v1(136.72,109.86) v1(137.16,44.45) v1(137.35,130.49) v1(137.67,100.77) v1(138.81,111.63) v1(139.19,83.31) v1(140.37,93.19) v1(140.34,91.19) v1(140.53,100.17) v1(141.22,44.45) v1(141.95,102.87) v1(142.11,93.19) v1(142.11,91.31) v1(142.75,104.62) v1(143.51,44.45) v1(143.86,93.19) v1(146.56,185.58) v1(147.57,44.45) v1(148.08,109.6) v1(149.86,44.45) v1(153.92,44.45) v1(154.79,169.66) v1(154.79,168.13) v1(154.79,166.36) v1(155.61,170.66) v1(155.59,168.86) v1(155.59,167.34) v1(155.85,165.48) v1(157.12,165.48) v1(175.11,172.2) v1(175.11,170.67) v1(175.11,168.9) v1(175.91,171.4) v1(175.91,169.88) v1(176.13,173.72) v1(176.17,168.02) v1(177.04,75.18) v1(177.04,71.5) v1(177.44,168.02) v1(180.21,141.86)
GNDE: length 354.4
  TOP w0.762: C99.2 v1(164.59,6.59) ; C123.2 v1(9.78,14.45) ; C119.2 v1(119.4,6.59) ; C121.2 v1(133.22,6.59) ; C122.2 v1(175.13,24.26) ; C101.2 v1(151.39,6.59)
  L2_GND w1.27: U8.34 24.36,177.35 ; U8.34 22.38,178.2 ; U8.34 24.08,178.2 ; U8.34 22.1,177.35 ; J9.7 146.62,203.29 ; J9.7 146.62,201.23 ; J9.7 144.56,203.29 ; J9.7 144.56,201.23 ; 36.63,193.2 U8.39 ; U8.39 38.33,191.5 ; U8.39 36.63,191.5 ; U8.39 38.33,193.2 ; U7.35 96.75,181.5 ; U7.35 96.75,183.2 ; U7.35 95.05,183.2 ; U7.35 95.05,181.5 ; 148.8,2.14 CON1.9 ; CON1.9 151.13,2.14 ; CON1.9 148.8,4.47 ; CON1.9 151.13,4.47 ; 80.54,177.82 U7.34 ; U7.34 80.8,178.2 ; U7.34 82.75,177.82 ; U7.34 82.5,178.2 ; CON1.10 135.43,4.47 ; CON1.10 133.1,4.47 ; CON1.10 133.1,2.14 ; CON1.10 135.43,2.14 ; 95.05,203.2 U7.41 ; U7.41 96.75,201.5 ; U7.41 96.75,203.2 ; U7.41 95.05,201.5 ; U8.42 29.75,203.2 ; U8.42 29.75,201.5 ; U8.42 28.05,203.2 ; U8.42 28.05,201.5 ; 95.05,191.5 U7.39 ; U7.39 96.75,193.2 ; U7.39 96.75,191.5 ; U7.39 95.05,193.2 ; 80.8,188.2 U7.38 ; U7.38 82.5,188.2 ; U7.38 82.5,186.5 ; U7.38 80.8,186.5 ; 131.25,203.29 J9.8 ; J9.8 133.31,203.29 ; J9.8 131.25,201.23 ; J9.8 133.31,201.23 ; U7.36 91.07,181.5 ; U7.36 89.37,181.5 ; U7.36 89.37,183.2 ; U7.36 91.07,183.2 ; U7.37 85.67,183.2 ; U7.37 85.67,181.5 ; U7.37 83.97,183.2 ; U7.37 83.97,181.5 ; U6.17 45.86,3.56 ; U6.17 43.67,5.74 ; U6.17 43.67,3.56 ; U6.17 44.77,3.17 ; 36.63,181.5 U8.35 ; U8.35 38.33,183.2 ; U8.35 36.63,183.2 ; U8.35 38.33,181.5 ; U8.40 24.08,198.2 ; U8.40 24.08,196.5 ; U8.40 22.38,198.2 ; U8.40 22.38,196.5 ; U7.40 82.5,196.5 ; U7.40 80.8,196.5 ; U7.40 80.8,198.2 ; U7.40 82.5,198.2 ; U7.42 88.17,203.2 ; U7.42 86.47,203.2 ; U7.42 86.47,201.5 ; U7.42 88.17,201.5 ; 30.95,181.5 U8.36 ; U8.36 30.95,183.2 ; U8.36 32.65,181.5 ; U8.36 32.65,183.2 ; 133.86,199.39 135.27,200.81 ; 133.86,199.39 132.44,200.81 ; 133.86,199.39 135.27,197.97 ; 133.86,199.39 132.44,197.97 ; 142.6,200.81 144.02,199.39 ; 144.02,199.39 142.6,197.97 ; 144.02,199.39 145.43,200.81 ; 144.02,199.39 145.43,197.97 ; U8.37 27.25,181.5 ; U8.37 27.25,183.2 ; U8.37 25.55,183.2 ; U8.37 25.55,181.5 ; 60.9,3.17 U6.18 ; U6.18 61.99,5.74 ; U6.18 61.99,3.56 ; U6.18 59.8,3.56 ; 36.63,201.5 U8.41 ; U8.41 38.33,203.2 ; U8.41 38.33,201.5 ; U8.41 36.63,203.2 ; 22.38,186.5 U8.38 ; U8.38 24.08,188.2 ; U8.38 22.38,188.2 ; U8.38 24.08,186.5
  L3_PWR1 w1.27: CON1.10 135.43,4.47 ; CON1.10 133.1,4.47 ; CON1.10 133.1,2.14 ; CON1.10 135.43,2.14 ; 44.77,3.17 U6.17 ; U6.17 45.86,3.56 ; U6.17 43.67,5.74 ; U6.17 43.67,3.56 ; 148.8,4.47 CON1.9 ; CON1.9 151.13,4.47 ; CON1.9 148.8,2.14 ; CON1.9 151.13,2.14 ; U6.18 61.99,5.74 ; U6.18 59.8,3.56 ; U6.18 61.99,3.56 ; U6.18 60.9,3.17
  L4_PWR2 w1.27: 133.1,2.14 CON1.10 ; CON1.10 133.1,4.47 ; CON1.10 135.43,4.47 ; CON1.10 135.43,2.14 ; 44.77,3.17 U6.17 ; U6.17 43.67,3.56 ; U6.17 43.67,5.74 ; U6.17 45.86,3.56 ; U6.18 61.99,5.74 ; U6.18 59.8,3.56 ; U6.18 61.99,3.56 ; U6.18 60.9,3.17 ; CON1.9 151.13,4.47 ; CON1.9 148.8,2.14 ; CON1.9 151.13,2.14 ; CON1.9 148.8,4.47
  L5_GND w1.27: 60.9,3.17 U6.18 ; U6.18 59.8,3.56 ; U6.18 61.99,3.56 ; U6.18 61.99,5.74 ; 80.8,178.2 U7.34 ; U7.34 82.75,177.82 ; U7.34 80.54,177.82 ; U7.34 82.5,178.2 ; J9.8 133.31,203.29 ; J9.8 133.31,201.23 ; J9.8 131.25,201.23 ; J9.8 131.25,203.29 ; U7.40 82.5,196.5 ; U7.40 80.8,196.5 ; U7.40 80.8,198.2 ; U7.40 82.5,198.2 ; 132.44,200.81 133.86,199.39 ; 133.86,199.39 132.44,197.97 ; 133.86,199.39 135.27,197.97 ; 133.86,199.39 135.27,200.81 ; 95.05,201.5 U7.41 ; U7.41 96.75,203.2 ; U7.41 96.75,201.5 ; U7.41 95.05,203.2 ; U7.37 85.67,183.2 ; U7.37 83.97,181.5 ; U7.37 85.67,181.5 ; U7.37 83.97,183.2 ; 36.63,181.5 U8.35 ; U8.35 36.63,183.2 ; U8.35 38.33,183.2 ; U8.35 38.33,181.5 ; U8.41 38.33,201.5 ; U8.41 38.33,203.2 ; U8.41 36.63,201.5 ; U8.41 36.63,203.2 ; 86.47,201.5 U7.42 ; U7.42 88.17,201.5 ; U7.42 88.17,203.2 ; U7.42 86.47,203.2 ; 30.95,183.2 U8.36 ; U8.36 30.95,181.5 ; U8.36 32.65,181.5 ; U8.36 32.65,183.2 ; U7.39 96.75,191.5 ; U7.39 96.75,193.2 ; U7.39 95.05,193.2 ; U7.39 95.05,191.5 ; 22.38,186.5 U8.38 ; U8.38 24.08,186.5 ; U8.38 24.08,188.2 ; U8.38 22.38,188.2 ; 148.8,2.14 CON1.9 ; CON1.9 151.13,4.47 ; CON1.9 151.13,2.14 ; CON1.9 148.8,4.47 ; 144.56,203.29 J9.7 ; J9.7 144.56,201.23 ; J9.7 146.62,201.23 ; J9.7 146.62,203.29 ; U8.39 38.33,191.5 ; U8.39 38.33,193.2 ; U8.39 36.63,191.5 ; U8.39 36.63,193.2 ; 89.37,183.2 U7.36 ; U7.36 91.07,181.5 ; U7.36 89.37,181.5 ; U7.36 91.07,183.2 ; 28.05,201.5 U8.42 ; U8.42 29.75,203.2 ; U8.42 28.05,203.2 ; U8.42 29.75,201.5 ; 22.1,177.35 U8.34 ; U8.34 22.38,178.2 ; U8.34 24.36,177.35 ; U8.34 24.08,178.2 ; 133.1,4.47 CON1.10 ; CON1.10 133.1,2.14 ; CON1.10 135.43,4.47 ; CON1.10 135.43,2.14 ; 95.05,181.5 U7.35 ; U7.35 96.75,183.2 ; U7.35 95.05,183.2 ; U7.35 96.75,181.5 ; U7.38 82.5,188.2 ; U7.38 80.8,188.2 ; U7.38 82.5,186.5 ; U7.38 80.8,186.5 ; U8.37 27.25,183.2 ; U8.37 27.25,181.5 ; U8.37 25.55,181.5 ; U8.37 25.55,183.2 ; U6.17 45.86,3.56 ; U6.17 43.67,5.74 ; U6.17 44.77,3.17 ; U6.17 43.67,3.56 ; U8.40 24.08,196.5 ; U8.40 22.38,196.5 ; U8.40 22.38,198.2 ; U8.40 24.08,198.2 ; 144.02,199.39 145.43,197.97 ; 144.02,199.39 142.6,197.97 ; 144.02,199.39 145.43,200.81 ; 144.02,199.39 142.6,200.81
  BOTTOM w0.762: R62.1 v1(9.78,14.45) ; C117.2 127.51,7.86 v1(127.51,6.73) ; C113.2 124.97,7.86 v1(124.97,6.73) ; C109.2 159.26,7.86 v1(159.26,6.73) ; R63.1 v1(175.13,24.26) ; C105.2 156.72,7.86 v1(156.72,6.73)
  vias: v1(143.38,19.11) v1(145.76,19.11)
SGND_U9: length 13.5
  TOP w0.254: U9.4 21.39,23.44 v1(21.62,23.21) ; C167.2 16.72,22.44 U9.11 U9.12 17.97,21.94 18.31,21.6 U9.13 18.31,21.28 v1(17.79,20.76)
  TOP w0.508: v1(17.79,20.76) 17.79,20.31 R113.1 R114.2
  BOTTOM w0.508: v1(17.79,20.76) 20.24,23.21 v1(21.62,23.21) 21.63,23.2 R115.2
SGND_U10: length 23.5
  TOP w0.254: C180.2 159.69,174.24 U10.11 U10.12 ; v1(154.83,173.56) 155.15,173.24 U10.4
  TOP w0.301: v1(158.62,175.89) 158.1,175.37 U10.13 158.1,175.14 158.51,174.74 U10.12
  TOP w0.508: v1(159.11,179.7) R118.2 159.1,178.43 159.1,176.37 v1(158.62,175.89)
  BOTTOM w0.508: R124.2 154.22,173.56 v1(154.83,173.56) 156.31,173.56 158.45,175.71 158.45,175.72 v1(158.62,175.89) ; R122.2 R121.2 R120.2 ; R120.2 R119.2 ; R120.2 159.11,180.66 v1(159.11,179.7)
SGND_U11: length 14
  TOP w0.254: C189.2 115.83,181.41 U11.11 U11.12 114.28,180.45 v1(114.18,180.34) 114.18,180.08 114.44,179.82 U11.13 ; v1(116.5,176.54) 116.83,176.87 U11.4
  TOP w0.508: v1(114.18,180.34) 113.7,180.82 R126.2 R128.2
  BOTTOM w0.406: v1(114.18,180.34) 114.17,180.34 116.5,178.01 v1(116.5,176.54)
  BOTTOM w0.508: R129.2 116.5,175.94 v1(116.5,176.54)
SGND_U12: length 14.8
  TOP w0.254: v1(174.97,176.05) 175.25,175.78 U12.4 ; C201.2 180.01,176.78 U12.11 U12.12 179,177.32 178.63,177.32 178.42,177.53 U12.13 178.42,178.13 178.68,178.39 179.37,178.39 v1(179.42,178.43)
  TOP w0.508: v1(179.42,178.43) 179.43,178.44 R132.1 R133.2
  BOTTOM w0.508: v1(179.42,178.43) 177.04,176.05 v1(174.97,176.05) 174.49,176.05 R134.2
VCC_3.3V: length 151.7
  TOP w0.254: U12.3 175.86,176.28 v1(175.15,176.99)
  TOP w0.508: R131.1 v1(175.62,182.88) ; D3.1 D2.1 D1.1 v1(88.18,30.4) ; R110.1 v1(14.48,34.8) ; R125.1 v1(111.63,167.33) ; D6.1 D5.1 v1(12.32,42.85) D4.1 v1(9.32,42.85)
  L4_PWR2 w0.914: J9.6 136.52,193.8 ; J9.6 135,193.8 ; J9.6 136.52,192.28 ; J9.6 135,192.28 ; J9.1 142.87,189.74 ; J9.1 142.87,191.26 ; J9.1 141.35,191.26 ; J9.1 141.35,189.74 ; 168.99,165.73 170.05,165.73 ; 170.05,165.73 169.25,166.54 ; 170.05,165.73 170.86,166.54 ; 170.05,165.73 170.05,166.8
  BOTTOM w0.508: v1(93.54,176.37) 93.54,175.71 C141.1 93.19,175.26 93.54,174.92 v1(93.54,174.15) ; v1(93.06,179.23) 92.74,179.23 92.26,179.71 R92.2 R91.2 R90.2 R89.2 R88.2 85.44,179.23 v1(84.96,179.23) ; v1(34.64,179.39) 34.01,179.39 R104.2 R103.2 R102.2 R101.2 R100.2 27.01,179.39 v1(26.38,179.39) ; L3.1 34.55,167.16 v1(35.43,167.16) 36.07,167.8 C150.1 ; C143.1 94.49,167.32 v1(94.01,166.85) 93.29,166.85 L1.1 92.81,167.55 93.53,168.27 v1(93.53,168.75) ; C151.1 v1(34.83,176.69) ; v1(84.49,168.75) 84.49,167.89 L2.2 84.57,166.85 v1(84.01,166.85) 83.38,167.48 C140.1 ; v1(9.32,42.85) v1(12.32,42.85) 21.16,42.85 31.62,32.39 84.2,32.39 86.19,30.4 v1(88.18,30.4) ; C153.1 25.43,167.63 v1(25.43,167.15) 25.44,167.16 26.47,167.16 L4.2
  vias: v1(168.55,173.1) v1(168.55,171.83) v1(168.55,170.56) v1(168.55,169.29) v1(168.55,168.02) v1(170.46,171.83) v1(170.46,170.56) v1(170.46,169.29) v1(170.46,168.02)
VCC_5V: length 26.7
  TOP w2.54: F1.2 TP15.1
  L3_PWR1 w0.914: JP42.1 165.14,170.35 ; JP42.1 165.14,168.74 ; JP42.1 163.53,170.35 ; JP42.1 163.53,168.74 ; 151.72,190.96 TP15.1 ; TP15.1 151.72,192.58 ; TP15.1 153.33,190.96 ; TP15.1 153.33,192.58 ; 119.72,186.86 120.52,186.05 ; 120.52,186.05 121.33,186.86 ; 120.52,186.05 121.33,185.25 ; 120.52,186.05 119.72,185.25 ; JP30.1 12.74,28.28 ; JP30.1 11.13,29.89 ; JP30.1 11.13,28.28 ; JP30.1 12.74,29.89 ; 183.85,172.89 JP51.1 ; JP51.1 185.46,171.28 ; JP51.1 185.46,172.89 ; JP51.1 183.85,171.28
  BOTTOM w0.508: R111.2 TP15.1
VDD_1.0V: length 10
  TOP w0.254: v1(115.62,176.54) 116.33,177.26 U11.3
  BOTTOM w0.152: v1(121.66,169.95) 122.67,169.95 R127.1
  BOTTOM w0.508: v1(115.62,176.54) 115.62,174.25 v1(119.28,170.58)
GEN_VDDO: length 32.6
  TOP w0.254: U10.3 155.54,173.74 v1(154.83,174.45)
  TOP w0.508: C51.1 148.85,179.32 v1(148.28,179.32) ; U3.4 58.26,183.07 58.77,182.56 v1(58.77,182.09) ; Y3.4 v1(82.42,95.69) ; Y1.4 v1(172.59,96.14)
  L3_PWR1 w0.914: 145.12,165.56 145.92,166.37 ; 145.92,166.37 145.12,167.18 ; 145.92,166.37 146.73,165.56 ; 145.92,166.37 146.73,167.18
  BOTTOM w0.508: R22.1 v1(137.03,182.88) ; C2.1 v1(173.07,103.35) ; v1(82.42,95.69) 81.69,95.69 C53.1 ; R145.1 v1(95.88,45.45) ; C1.1 172.57,96.16 v1(172.59,96.14) ; R148.2 v1(17.65,57.78) ; C52.1 v1(84.83,98.4) ; R117.1 v1(156.87,163.83) ; U4.14 v1(148.28,179.32) ; U4.1 v1(142.88,179.32) ; U4.4 v1(142.75,183.13) ; C5.1 58.8,182.11 v1(58.77,182.09) 58.77,181.35 C4.1 ; R2.1 v1(75.29,181.61) ; R1.1 v1(75.29,179.07) ; R24.1 v1(24.77,92.08) ; R8.1 v1(101.09,90.4)
  vias: v1(148.46,168.91) v1(148.46,167.64) v1(148.46,166.37) v1(148.46,165.1) v1(149.73,168.91) v1(149.73,167.64) v1(149.73,166.37) v1(149.73,165.1) v1(151,167.64)
MDC: length 16.3
  BOTTOM w0.152: U4.2 145.07,180.59 145.45,180.97 145.45,183.99 145.03,184.4 U4.5 143.64,184.4 TP6.1 J9.2
MDIO: length 217.5
  TOP w0.152: v1(45.28,91.44) 45.53,91.19 U2.8 ; v1(137.67,109.86) 137.67,111 135.89,112.78 135.89,135.38 134.11,137.16 134.11,140.72 132.59,142.24 TP7.1 ; v1(134.49,92.08) 135.38,91.19 U1.8
  BOTTOM w0.152: v1(137.67,109.86) 137.67,103.51 135.64,101.47 135.64,93.22 v1(134.49,92.08) 134.49,91.95 132.97,90.42 126.87,90.42 125.48,91.82 99.31,91.82 94.49,87 94.49,82.93 90.93,79.38 70.83,79.38 65.37,84.84 50.55,84.84 47.12,88.27 47.12,89.6 v1(45.28,91.44) R23.1 ; J9.5 R22.2 134.15,188.76 TP7.1
U1_1.8V: length 18.2
  L3_PWR1 w0.914: 123.91,39.58 JP28.1 ; JP28.1 125.52,39.58 ; JP28.1 125.52,41.19 ; JP28.1 123.91,41.19 ; JP25.1 159.43,39.58 ; JP25.1 157.82,39.58 ; JP25.1 159.43,41.19 ; JP25.1 157.82,41.19 ; JP27.1 125.52,30.69 ; JP27.1 123.91,30.69 ; JP27.1 125.52,32.3 ; JP27.1 123.91,32.3 ; JP26.1 165.78,41.19 ; JP26.1 164.17,41.19 ; JP26.1 164.17,39.58 ; JP26.1 165.78,39.58
U1_AVDD_1.8V: length 22.4
  TOP w0.3: U1.38 145.37,92.69 145.16,92.48 v1(145.16,92.46)
  TOP w0.301: v1(140.64,88.39) 140.86,88.17 U1.19 ; v1(144.65,88.42) 144.36,88.13 U1.26
  TOP w0.508: C156.1 v1(188.47,52.7)
  L4_PWR2 w0.914: 157.82,48.47 TP14.1 ; TP14.1 159.43,48.47 ; TP14.1 157.82,50.08 ; TP14.1 159.43,50.08
  BOTTOM w0.508: C39.1 v1(147.19,77.57) ; C35.1 145.26,92.36 v1(145.16,92.46) ; C38.1 v1(143.54,77.57) ; v1(144.65,88.42) 144.79,88.29 C34.1 ; C36.1 v1(141.16,80.76) ; C157.1 TP14.1 C158.1 ; C37.1 v1(167.14,81.29) ; v1(146.71,86.52) R9.2 v1(146.71,84.45) ; C40.1 v1(142.93,83.32) ; C33.1 140.54,88.29 v1(140.64,88.39)
  BOTTOM w2.032: L5.1 TP14.1
U1_AVDD_3.3V: length 17.4
  TOP w0.301: v1(141.61,88.37) 141.61,88.32 141.36,88.07 U1.20 ; U1.25 143.86,88.19 143.74,88.32 v1(143.74,88.4)
  TOP w0.508: C203.1 v1(107.8,73.41)
  L3_PWR1 w0.914: TP27.1 100.5,63.67 ; TP27.1 98.89,63.67 ; TP27.1 98.89,62.06 ; TP27.1 100.5,62.06
  BOTTOM w0.508: C45.1 v1(142.93,80.46) ; v1(143.74,88.4) 143.66,88.4 143.6,88.45 C43.1 ; C204.1 99.72,62.84 TP27.1 C206.1 ; C44.1 v1(141.16,77.57) ; C41.1 141.77,88.56 141.66,88.44 141.66,88.42 v1(141.61,88.37) ; C42.1 v1(141.16,83.94)
  BOTTOM w2.032: TP27.1 L21.1
U1_AVDDC_1.8V: length 14.2
  TOP w0.3: U1.35 145.36,91.19 145.22,91.06 v1(145.16,91.06)
  L3_PWR1 w0.914: TP16.1 165.78,48.47 ; TP16.1 164.17,48.47 ; TP16.1 165.78,50.08 ; TP16.1 164.17,50.08
  BOTTOM w0.508: v1(145.16,91.06) 145.16,90.22 C32.1 ; C162.1 TP16.1 C161.1 ; C31.1 v1(157.72,87.62) ; C30.1 v1(147.19,71.91) ; C29.1 v1(146.43,87.43)
  BOTTOM w2.032: L6.1 TP16.1
U1_AVDDF_1.8V: length 14.1
  TOP w0.3: U1.3 v1(139.04,93.69)
  L4_PWR2 w0.914: 123.91,50.08 TP17.1 ; TP17.1 125.52,48.47 ; TP17.1 125.52,50.08 ; TP17.1 123.91,48.47
  BOTTOM w0.508: C25.1 139.04,93.69 v1(139.04,93.69) ; C26.1 v1(136.07,76.46) ; C27.1 v1(130.31,95.73) ; C163.1 TP17.1 C164.1 ; C28.1 v1(134.31,95.85)
  BOTTOM w2.032: L8.1 TP17.1
U1_CLK125: length 46.1
  TOP w0.152: U1.9 133.21,90.69 132.46,91.44 v1(129.41,91.44)
  BOTTOM w0.152: J2.1 119,101.85 v1(129.41,91.44)
  BOTTOM w0.508: C14.1 J2.1
U1_CONFIG: length 80
  TOP w0.152: JP57.1 R149.1 85.76,43.56 90.8,43.56 102.23,54.99 102.23,61.09 106.3,65.15 114.81,65.15 121.28,71.63 127.89,71.63 137.67,81.41 137.67,83.82 138.86,85.01 U1.15
U1_LED_0: length 77.1
  TOP w0.152: v1(107.7,67.56) 112.9,67.56 132.21,86.87 134.62,86.87 135.94,88.19 U1.14
  BOTTOM w0.152: v1(107.7,67.56) 104.9,64.77 104.9,56.13 90.8,42.04 JP11.5 89.53,40.01 R28.2
U1_LED_1: length 78.2
  TOP w0.152: U1.13 135.68,88.69 134.49,87.5 131.67,87.5 119.22,75.06 v1(117.09,75.06) ; JP11.3 94.61,40.01 99.69,40.01 JP56.1 R163.1
  BOTTOM w0.152: v1(117.09,75.06) 117.09,58.42 100.97,42.29 JP56.1
U1_LED_2: length 74.4
  TOP w0.152: INTN_1.1 98.42,44.45 JP12.1 ; U1.12 135.54,89.19 134.42,88.06 131.11,88.06 123.7,80.65 v1(115.44,80.65)
  BOTTOM w0.152: INTN_1.1 107.95,53.98 110.87,53.98 115.44,58.55 v1(115.44,80.65)
U1_MDC: length 110.4
  TOP w0.152: v1(136.78,91.95) 137.04,91.69 U1.7 ; v1(147.19,109.6) 147.19,111.63 155.45,119.89 155.45,135.13 152.65,137.92 149.86,137.92 141.86,145.92 141.86,180.97 v1(142.75,181.86)
  BOTTOM w0.152: v1(147.19,109.6) 147.19,102.23 141.8,96.84 137.99,96.84 136.78,95.63 v1(136.78,91.95) ; v1(142.75,181.86) U4.3
U1_MDI_N_0: length 47.6
  TOP w0.127: U1.27 144.9,87.46 144.9,84.47 146.76,82.6 146.76,80.78 151.66,75.88 151.66,45.82 151.66,45.69 151.28,45.31 v1(149.9,45.31)
  BOTTOM w0.127: R41.2 v1(149.9,45.31)
U1_MDI_N_1: length 45.8
  TOP w0.127: v1(143.55,45.31) 144.93,45.31 144.93,45.31 145.31,45.69 145.31,45.82 145.31,82.04 142.93,84.42 142.93,87.42 U1.23
  BOTTOM w0.127: R45.2 v1(143.55,45.31)
U1_MDI_N_2: length 46.1
  TOP w0.127: v1(137.2,45.31) 138.58,45.31 138.96,45.69 138.96,45.82 138.96,69.85 140.05,70.94 141.9,72.79 141.9,87.46 U1.21
  BOTTOM w0.127: R51.2 v1(137.2,45.31)
U1_MDI_N_3: length 47.6
  TOP w0.127: v1(131,45.31) 132.24,45.31 132.62,45.69 132.62,69.22 139.9,76.5 139.9,87.46 U1.17
  BOTTOM w0.127: R57.2 v1(131,45.31)
U1_MDI_P_0: length 47.6
  TOP w0.127: U1.28 145.33,87.45 145.33,84.65 147.19,82.78 147.19,80.96 152.09,76.06 152.09,45.82 152.09,45.69 152.47,45.31 v1(153.85,45.3)
  BOTTOM w0.127: R40.1 v1(153.85,45.3)
U1_MDI_P_1: length 45.8
  TOP w0.127: U1.24 143.36,84.6 145.74,82.22 145.74,45.82 145.74,45.69 146.12,45.31 146.12,45.31 v1(147.5,45.3)
  BOTTOM w0.127: R39.1 v1(147.5,45.3)
U1_MDI_P_2: length 46.1
  TOP w0.127: U1.22 142.33,87.46 142.33,72.61 139.39,69.67 139.39,45.82 139.39,45.69 139.77,45.31 v1(141.15,45.3)
  BOTTOM w0.127: R48.1 v1(141.15,45.3)
U1_MDI_P_3: length 47.6
  TOP w0.127: U1.18 140.33,87.46 140.33,76.32 133.05,69.04 133.05,45.69 133.43,45.31 v1(134.68,45.31)
  BOTTOM w0.127: R55.2 v1(134.68,45.31)
U1_RESETN: length 138.2
  TOP w0.152: v1(121.79,84.61) 121.79,95.41 104.52,112.68 104.52,117.86 v1(85.85,136.53) ; v1(85.85,141.1) 80.52,146.43 80.52,163.19 79.25,164.47 79.25,170.81 JP3.4 ; v1(139.19,84.2) 139.36,84.37 U1.16
  BOTTOM w0.152: v1(121.79,84.61) 138.78,84.61 v1(139.19,84.2) ; v1(85.85,136.53) v1(85.85,141.1) ; R1.2 JP3.4
U1_RX_CLK: length 43
  TOP w0.152: v1(142.75,103.51) 139.57,106.68 139.57,110.24 142.24,112.9 142.24,125.86 139.57,128.52 139.57,131.92 R140.1 ; U1.46 143.86,99.41 144.65,100.2 v1(144.65,100.97)
  BOTTOM w0.152: v1(144.65,100.97) 142.75,102.87 v1(142.75,103.51)
U1_RX_CLK1: length 2.6
  TOP w0.152: JP23.11 140.68,134.78 R140.2
U1_RX_CTRL: length 42.6
  TOP w0.152: JP23.1 152.27,133.35 152.27,118.24 146.56,112.52 146.56,98.93 145.36,97.74 U1.43
U1_RXD_0: length 43
  TOP w0.152: U1.44 144.86,98 145.92,99.06 145.92,113.28 151,118.36 151,129.54 149.56,130.98 149.56,133.18 JP23.3
U1_RXD_1: length 43
  TOP w0.152: U1.45 144.36,98.52 145.29,99.44 145.29,114.05 149.73,118.49 149.73,128.27 147.19,130.81 147.19,133.35 JP23.5
U1_RXD_2: length 42.9
  TOP w0.152: JP23.7 144.65,133.35 144.65,130.81 147.83,127.64 147.83,117.98 144.65,114.81 144.65,102.23 143.36,100.95 U1.47
U1_RXD_3: length 43.1
  TOP w0.152: U1.48 142.86,101.59 144.02,102.75 144.02,115.57 146.56,118.11 146.56,126.37 142.11,130.81 142.11,133.35 JP23.9
U1_SIN_N: length 77.6
  TOP w0.127: U1.2 138.13,94.22 133.14,94.22 119.33,108.03 119.33,120.32 107.31,132.33 104.52,132.33 92.74,144.11 92.74,147.31 R86.2
U1_SIN_N_U2_SOUT_N: length 103.1
  TOP w0.127: R109.1 v1(14.51,111.81) ; R87.1 v1(91.95,145.41)
  BOTTOM w0.127: v1(91.95,145.41) 92.76,144.6 92.76,143.67 92.02,142.93 33.48,142.93 15.35,124.8 15.35,112.07 15.09,111.81 v1(14.51,111.81)
U1_SIN_P: length 76.9
  TOP w0.127: U1.1 138.13,94.66 133.32,94.66 119.76,108.21 119.76,120.5 107.49,132.77 104.7,132.77 93.17,144.29 93.17,147.28 C136.1 R84.2
U1_SIN_P_U2_SOUT_P: length 103.3
  TOP w0.127: R106.1 v1(16.73,111.66) ; R84.1 v1(94.01,145.41)
  BOTTOM w0.127: v1(94.01,145.41) 93.2,144.6 93.2,143.49 92.2,142.49 33.66,142.49 15.78,124.62 15.78,112.13 16.25,111.66 v1(16.73,111.66)
U1_SOUT_N: length 95
  TOP w0.127: R95.2 72.74,152.39 72.74,149.38 83.44,138.68 87.27,138.68 107.52,118.44 107.52,115.39 130.15,92.76 138.09,92.76 U1.5
U1_SOUT_N_U2_SIN_N: length 67.5
  TOP w0.127: v1(71.79,150.8) R96.1
  TOP w0.152: R105.1 v1(14.64,146.99)
  BOTTOM w0.127: v1(71.79,150.8) 71.8,150.81 72.71,150.81 72.84,150.94 72.84,151.85 72.08,152.6 43.38,152.6 35.31,144.53 16.64,144.53 15.59,145.57 15.59,146.69 15.28,146.99 v1(14.64,146.99)
U1_SOUT_P: length 94.3
  TOP w0.127: C145.2 73.17,152.52 73.17,149.56 83.62,139.12 87.45,139.12 107.95,118.62 107.95,115.57 130.33,93.19 U1.4
U1_SOUT_P_U2_SIN_P: length 67
  TOP w0.127: v1(74.01,150.8) R93.1
  TOP w0.152: R97.1 v1(16.86,146.99)
  BOTTOM w0.127: v1(74.01,150.8) 74,150.81 73.46,150.81 73.27,151 73.27,152.03 72.26,153.03 43.2,153.03 35.13,144.96 16.82,144.96 16.02,145.75 16.02,146.74 16.27,146.99 v1(16.86,146.99)
U1_TX_CLK: length 51.6
  TOP w0.152: v1(137.53,99.39) 137.03,99.89 137.03,102.23 122.43,116.84 122.43,133.35 JP55.11 118.77,134.62 R142.1 ; v1(140.54,99.22) 140.36,99.04 U1.53
  BOTTOM w0.152: v1(137.53,99.39) 137.71,99.22 v1(140.54,99.22)
U1_TX_CLK1: length 70.7
  TOP w0.152: R142.2 v1(118.62,131.44) ; v1(83.06,131.44) 59.82,131.44 56.9,128.52 JP24.11
  BOTTOM w0.152: v1(83.06,131.44) 84.96,131.44 89.53,136.02 114.05,136.02 v1(118.62,131.44)
U1_TX_CTRL: length 123.9
  TOP w0.152: U1.56 138.86,96.21 138.46,96.62 v1(138.46,100.17) ; JP55.1 135.13,133.35 135.13,125.57 134.8,125.25 133.55,125.25 133.22,124.93 133.22,124.47 133.55,124.14 134.8,124.14 135.13,123.82 135.13,123.36 134.8,123.04 133.55,123.04 133.22,122.72 133.22,122.26 133.55,121.94 134.8,121.94 135.13,121.61 135.13,109.86 141.22,103.76 141.22,102.65 v1(141.95,101.92) ; v1(81.79,128.27) 71.88,128.27 JP24.1
  BOTTOM w0.152: v1(141.95,101.92) 140.21,101.92 v1(138.46,100.17) ; JP55.1 133.86,133.98 132.59,132.72 132.59,130.81 130.05,128.27 116.71,128.27 112.78,132.21 91.82,132.21 87.88,128.27 v1(81.79,128.27)
U1_TXD_0: length 122.2
  TOP w0.152: JP24.3 69.98,128.91 v1(83.06,128.91) ; U1.50 141.86,100.83 140.72,101.98 140.72,103.12 132.59,111.25 132.59,126.39 132.91,126.72 134.17,126.72 134.49,127.04 134.49,127.5 134.17,127.82 132.91,127.82 132.59,128.15 132.59,128.6 132.91,128.93 134.17,128.93 134.49,129.25 134.49,129.71 134.17,130.03 132.91,130.03 132.59,130.36 132.59,133.35 JP55.3
  BOTTOM w0.152: JP55.3 131.32,133.98 130.05,132.72 130.05,131.19 127.76,128.91 116.97,128.91 112.9,132.97 90.8,132.97 86.74,128.91 v1(83.06,128.91)
U1_TXD_1: length 123.3
  TOP w0.152: JP55.5 130.05,133.35 130.05,130.56 130.37,130.24 131.63,130.24 131.95,129.91 131.95,129.46 131.63,129.13 130.37,129.13 130.05,128.81 130.05,128.35 130.37,128.03 131.63,128.03 131.95,127.7 131.95,127.25 131.63,126.92 130.37,126.92 130.05,126.6 130.05,112.78 140.21,102.62 140.21,101.73 141.36,100.57 U1.51 ; v1(81.79,129.54) 68.07,129.54 JP24.5
  BOTTOM w0.152: JP55.5 128.78,133.86 127.51,132.59 127.51,131.06 125.98,129.54 117.09,129.54 112.78,133.86 90.68,133.86 86.36,129.54 v1(81.79,129.54)
U1_TXD_2: length 123.7
  TOP w0.152: U1.54 139.86,98.14 139.7,98.3 139.7,101.85 127.51,114.05 127.51,126.68 127.83,127 129.09,127 129.41,127.33 129.41,127.78 129.09,128.11 127.83,128.11 127.51,128.43 127.51,128.89 127.83,129.21 129.09,129.21 129.41,129.54 129.41,129.99 129.09,130.32 127.83,130.32 127.51,130.64 127.51,133.35 JP55.7 ; JP24.7 66.17,130.18 v1(83.06,130.18)
  BOTTOM w0.152: v1(83.06,130.18) 85.98,130.18 90.42,134.62 113.03,134.62 117.47,130.18 123.83,130.18 124.97,131.32 124.97,132.72 126.24,133.98 JP55.7
U1_TXD_3: length 124.6
  TOP w0.152: JP24.9 64.26,130.81 v1(84.33,130.81) ; JP55.9 124.97,133.35 124.97,130.72 125.29,130.4 126.55,130.4 126.87,130.08 126.87,129.62 126.55,129.29 125.29,129.29 124.97,128.97 124.97,128.51 125.29,128.19 126.55,128.19 126.87,127.87 126.87,127.41 126.55,127.09 125.29,127.09 124.97,126.76 124.97,115.57 139.26,101.28 139.26,96.65 139.36,96.54 U1.55
  BOTTOM w0.152: v1(84.33,130.81) 85.6,130.81 90.17,135.38 113.03,135.38 117.6,130.81 121.79,130.81 122.43,131.44 122.43,132.72 123.7,133.98 JP55.9
U1_V18: length 40
  TOP w0.152: U1.10 128.04,90.19 127.13,89.28 v1(123.83,89.28)
  BOTTOM w0.152: v1(123.83,89.28) 103.89,89.28 JP4.1 R8.2
U1_VDD_1.0V: length 65.8
  TOP w0.152: v1(147.99,95.25) 152.43,95.25 164.97,107.79 C15.1
  TOP w0.3: U1.6 v1(138.99,92.19) ; U1.40 v1(145.16,93.69)
  TOP w0.301: v1(147.99,95.25) 147.19,95.25 146.63,94.69 U1.42
  TOP w2.032: L15.1 TP23.1
  L4_PWR2 w0.914: TP23.1 137.08,154.48 ; TP23.1 135.47,152.86 ; TP23.1 135.47,154.48 ; TP23.1 137.08,152.86
  BOTTOM w0.508: v1(147.99,95.25) 148.01,95.28 C10.1 ; C8.1 v1(146.59,96.07) ; C11.1 v1(157.72,95.87) ; C185.1 TP23.1 C186.1 ; C12.1 v1(151.14,109.61) ; v1(138.99,92.19) 138.97,92.21 C13.1 ; v1(145.16,93.69) 145.76,93.69 C9.1
